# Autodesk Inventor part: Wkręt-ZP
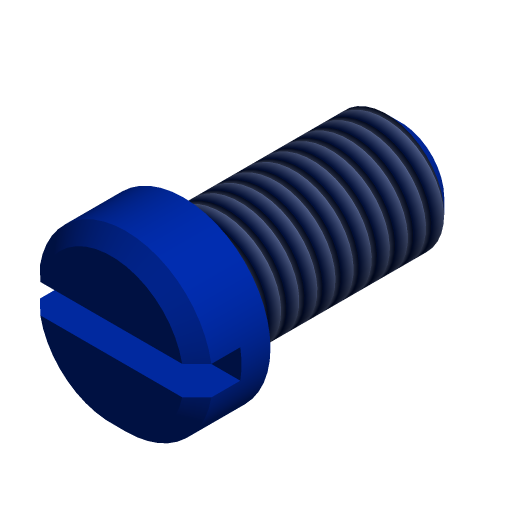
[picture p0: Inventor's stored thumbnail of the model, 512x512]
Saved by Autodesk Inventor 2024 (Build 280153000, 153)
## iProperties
Company: ATC
Shininess: 0.0
Length Units: 11269
Angle Units: 11279
Time Units: 11290
Mass Units: 11283
Length Display Precision: 3
Angle Display Precision: 2
Compacted: True
Created: 2023-03
Part Number: Wkręt-ZP
Document SubType Name: Modeling
Designer: Andrzej Jaskulski
Density: 1 g/cm^3
Material: Default
Appearance: Blue(Flat)
Checked By: A.J.
Engr Approved By: Andrzej Jaskulski
Mfg Approved By: Andrzej Jaskulski
Authority: A.J.
Density: 0.0
Volumn: 0.0
Area: 0.0
PropertySet Name: Model Information
Control State: 0
Master: False
Checked Out: False
Title: A.J.: Kurs R2024-MEP
Author: Andrzej Jaskulski
Revision Number: 1/24
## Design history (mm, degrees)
node "Extrusion1" dims "d1" = 15, "d2" = 0
  sketch "Sketch1"
    geometry: C1 r 4 at (0, 0)
    constraints: 1 centre point
    dimensions: "d0" = 8 diameter of C1
node "Extrusion2" dims "d4" = 5, "d5" = 0
  sketch "Sketch2"
    geometry: C1 r 4 at (0, 0) reference; C2 r 6 at (0, 0)
    constraints: 1 centre point, 1 coincident
    dimensions: "d3" = 12 diameter of C2
node "Chamfer1" dims "d6" = 1, "d7" = 1, "d39" = 45 deg
workplane "Work Plane2"
node "Extrusion3" dims "d11" = 5, "d12" = 0
  sketch "Sketch3"
    geometry: L1 (-1, 5)-(1, 5); L2 (1, 5)-(1, 2); L3 (1, 2)-(-1, 2); L4 (-1, 2)-(-1, 5); L5 (0, 2)-(0, 8)
    constraints: 10 end point, 3 parallel, 1 horizontal, 1 midpoint, 1 perpendicular
    dimensions: "d8" = 3 distance of L1.end L2.end; "d10" = 1 distance between parallel lines of L2 L5
thread "Thread1" dims "d37" = 10, "d38" = 0
node "Bryła1"
node "Korpusy bryłowe"
node "Korpusy powierzchniowe"
other parameters: "p" = 1.25 [user parameter], "de" = 8 [user parameter], "de1" = 6.647 [user parameter], "de2" = 7.188 [user parameter]
